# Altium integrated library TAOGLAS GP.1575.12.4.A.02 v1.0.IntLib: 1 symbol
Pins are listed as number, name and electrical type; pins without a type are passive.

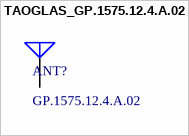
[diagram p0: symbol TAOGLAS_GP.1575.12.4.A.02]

## TAOGLAS_GP.1575.12.4.A.02
designator ANT?, comment GP.1575.12.4.A.02
ANTENNA PATCH GPS PIN FED 4mm thick GPS/GALILEO Patch Antenna, 1575MHz; ComponentLibStatus: Created; MFG: Taoglas; Temp_High: +85C; Temp_Low: -40C
footprint TAOGLAS_GP.1575.12.4.A.02 (4mm thick GPS/GALILEO Patch Antenna, 1575MHz)
pins: 1 A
